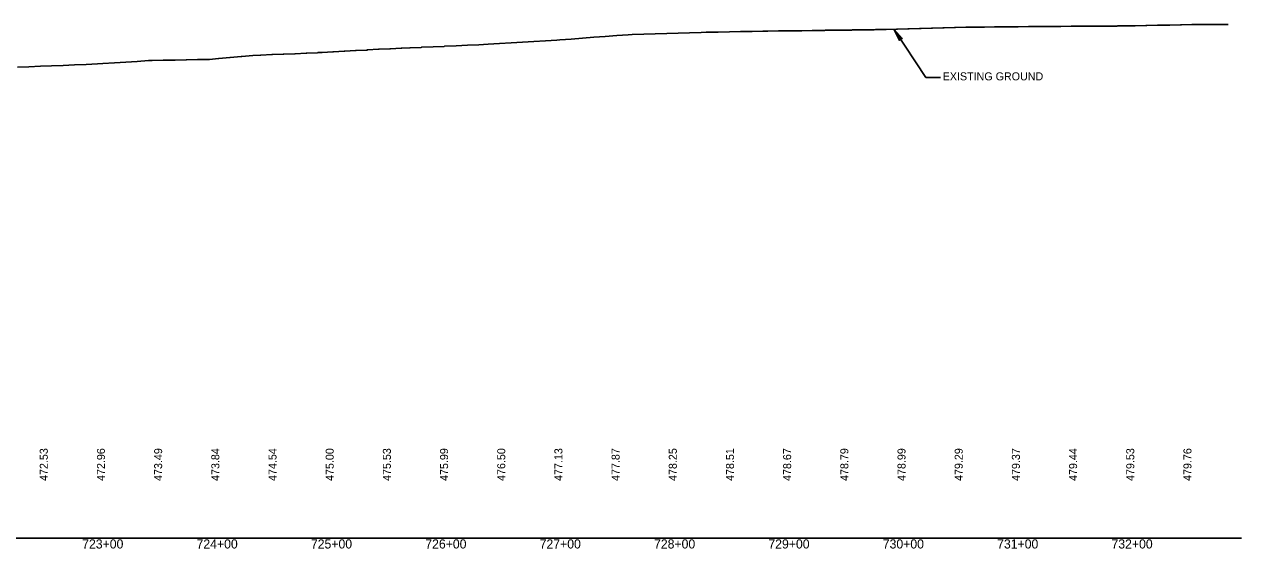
# Model space of a CAD drawing. Extents: x 2017200 to 2047700, y 854850 to 893350.
# Drawn here: x 2025936 to 2027000, y 889091 to 889549 of the extents above; entities that cross this region are included whole.
import ezdxf

# ---------------------------------------------------------------- set-up
doc = ezdxf.new("R2010")
doc.units = 0
for name, color, linetype in [('RD_DDB_Profile_EX', 7, 'Continuous'), ('RD_DDB_Profile_Lbl', 7, 'Continuous'), ('RD_DDB_StaTX', 7, 'Continuous'), ('RD_DDB_StripGrade', 7, 'Continuous'), ('RD_GPK_Profile_Cell', 7, 'Continuous')]:
    doc.layers.add(name, color=color, linetype=linetype)

msp = doc.modelspace()

# ---------------------------------------------------------------- linework, layer by layer
at = {"layer": 'RD_DDB_Profile_EX'}
msp.add_lwpolyline([(2025929.6, 889511.4), (2025939.6, 889511.8), (2025949.6, 889512.3), (2025959.5, 889512.7), (2025969.5, 889513.1), (2025979.6, 889513.5), (2025989.6, 889513.9), (2025999.6, 889514.3), (2026004.2, 889514.6), (2026014.4, 889515.3), (2026024.4, 889515.9), (2026034.4, 889516.6), (2026044.1, 889517.2), (2026047.4, 889517.3), (2026057.1, 889517.5), (2026057.4, 889517.5), (2026067.1, 889517.7), (2026067.4, 889517.7), (2026077.1, 889517.9), (2026077.4, 889517.9), (2026087.1, 889518.1), (2026087.4, 889518.1), (2026097.1, 889518.3), (2026097.4, 889518.3), (2026105.3, 889519), (2026105.7, 889519.1), (2026115.3, 889520), (2026115.7, 889520), (2026125.3, 889520.9), (2026125.7, 889520.9), (2026135.3, 889521.8), (2026142, 889522), (2026142.5, 889522.1), (2026152, 889522.5), (2026152.5, 889522.5), (2026162, 889522.9), (2026162.5, 889522.9), (2026172, 889523.3), (2026172.5, 889523.3), (2026182, 889523.7), (2026182.5, 889523.8), (2026192, 889524.1), (2026192.3, 889524.2), (2026195.3, 889524.3), (2026195.9, 889524.4), (2026205.3, 889524.9), (2026205.9, 889524.9), (2026215.3, 889525.4), (2026215.9, 889525.5), (2026225.3, 889526), (2026225.8, 889526), (2026235.2, 889526.5), (2026235.8, 889526.6), (2026245.2, 889527.1), (2026245.8, 889527.1), (2026255.2, 889527.6), (2026255.8, 889527.6), (2026265.1, 889528.1), (2026265.6, 889528.1), (2026272.6, 889528.4), (2026273.1, 889528.4), (2026282.6, 889528.8), (2026282.9, 889528.9), (2026283.2, 889528.9), (2026293, 889529.3), (2026302.7, 889529.7), (2026303, 889529.8), (2026313.2, 889530.2), (2026323.2, 889530.6), (2026333, 889531), (2026341.2, 889531.5), (2026351.2, 889532.1), (2026361.2, 889532.7), (2026371.2, 889533.4), (2026381.2, 889534), (2026391.3, 889534.6), (2026401.2, 889535.2), (2026403.7, 889535.4), (2026413.7, 889536.1), (2026423.7, 889536.9), (2026433.7, 889537.6), (2026443.6, 889538.4), (2026453.6, 889539.1), (2026463.6, 889539.8), (2026467.2, 889540), (2026477.2, 889540.3), (2026487.3, 889540.6), (2026497.3, 889540.9), (2026507.3, 889541.2), (2026517.3, 889541.6), (2026527.3, 889541.9), (2026531.8, 889542), (2026541.5, 889542.2), (2026542.2, 889542.2), (2026552.1, 889542.4), (2026561.8, 889542.6), (2026562.2, 889542.6), (2026571.9, 889542.8), (2026581.3, 889543), (2026581.9, 889543.1), (2026585, 889543.1), (2026585.6, 889543.1), (2026595, 889543.2), (2026595.7, 889543.2), (2026605, 889543.3), (2026605.7, 889543.3), (2026615, 889543.4), (2026615.3, 889543.4), (2026624.5, 889543.5), (2026625.3, 889543.5), (2026634.5, 889543.6), (2026635.3, 889543.6), (2026636, 889543.7), (2026645.1, 889543.8), (2026648.7, 889543.8), (2026649.6, 889543.9), (2026658.8, 889543.9), (2026659.8, 889544), (2026668.8, 889544.1), (2026669.8, 889544.1), (2026678.8, 889544.2), (2026679.8, 889544.3), (2026688.8, 889544.4), (2026689.3, 889544.4), (2026698.2, 889544.7), (2026699.2, 889544.7), (2026708.2, 889545), (2026709.2, 889545), (2026718.2, 889545.3), (2026719.2, 889545.3), (2026719.8, 889545.4), (2026728.8, 889545.6), (2026729.8, 889545.6), (2026738.8, 889545.9), (2026739.8, 889545.9), (2026748.8, 889546.2), (2026749.8, 889546.2), (2026758.8, 889546.5), (2026759.1, 889546.5), (2026764, 889546.6), (2026765.1, 889546.6), (2026774, 889546.6), (2026775.1, 889546.6), (2026784, 889546.7), (2026785.1, 889546.7), (2026794, 889546.8), (2026795, 889546.8), (2026804, 889546.8), (2026804.5, 889546.8), (2026813.5, 889546.9), (2026814.5, 889546.9), (2026823.5, 889547), (2026824.5, 889547), (2026833.6, 889547), (2026834.5, 889547.1), (2026840.9, 889547.1), (2026841.8, 889547.1), (2026850.9, 889547.2), (2026851.6, 889547.2), (2026860.7, 889547.2), (2026861.6, 889547.2), (2026870.8, 889547.3), (2026871.6, 889547.3), (2026880.8, 889547.4), (2026881.6, 889547.4), (2026890.8, 889547.4), (2026891.6, 889547.5), (2026900.8, 889547.5), (2026901.6, 889547.5), (2026906.2, 889547.6), (2026907, 889547.7), (2026916.2, 889547.9), (2026917.1, 889547.9), (2026926.4, 889548.1), (2026927.3, 889548.1), (2026936.4, 889548.3), (2026937.3, 889548.3), (2026946.4, 889548.5), (2026947.4, 889548.6), (2026956.4, 889548.8), (2026957.1, 889548.8), (2026958.1, 889548.8), (2026967, 889548.8), (2026968.2, 889548.9), (2026977, 889548.9), (2026977.7, 889548.9), (2026986.4, 889548.9), (2026987.8, 889548.9), (2026988.2, 889548.9)], dxfattribs=at)
at = {"layer": 'RD_DDB_Profile_Lbl'}
for p, q in [((2026723.8, 889502.6), (2026696.3, 889544.4)), ((2026736.7, 889502.6), (2026723.8, 889502.6))]:
    msp.add_line(p, q, dxfattribs=at)
msp.add_lwpolyline([(2026696.3, 889544.4), (2026700.8, 889534.9), (2026701.2, 889537), (2026703.3, 889536.5)], close=True, dxfattribs=at)
at = {"layer": 'RD_GPK_Profile_Cell'}
msp.add_line((2020500, 889100), (2027000, 889100), dxfattribs=at)

# ---------------------------------------------------------------- texts
at = {"layer": 'RD_DDB_Profile_Lbl'}
msp.add_text('EXISTING GROUND', height=7, dxfattribs=at).set_placement((2026738.6, 889500))
at = {"layer": 'RD_DDB_StaTX'}
for s, p in [('723+00', (2025986.2, 889091)), ('724+00', (2026086.2, 889091)), ('725+00', (2026186.2, 889091)), ('726+00', (2026286.2, 889091)), ('727+00', (2026386.2, 889091)), ('728+00', (2026486.2, 889091)), ('729+00', (2026586.2, 889091)), ('730+00', (2026686.2, 889091)), ('731+00', (2026786.2, 889091)), ('732+00', (2026886.2, 889091))]:
    msp.add_text(s, height=8, dxfattribs=at).set_placement(p)
at = {"layer": 'RD_DDB_StripGrade'}
for s, p in [('472.53', (2025956.1, 889150)), ('472.96', (2026006.1, 889150)), ('473.49', (2026056.1, 889150)), ('473.84', (2026106.1, 889150)), ('474.54', (2026156.1, 889150)), ('475.00', (2026206.1, 889150)), ('475.53', (2026256.1, 889150)), ('475.99', (2026306.1, 889150)), ('476.50', (2026356.1, 889150)), ('477.13', (2026406.1, 889150)), ('477.87', (2026456.1, 889150)), ('478.25', (2026506.1, 889150)), ('478.51', (2026556.1, 889150)), ('478.67', (2026606.1, 889150)), ('478.79', (2026656.1, 889150)), ('478.99', (2026706.1, 889150)), ('479.29', (2026756.1, 889150)), ('479.37', (2026806.1, 889150)), ('479.44', (2026856.1, 889150)), ('479.53', (2026906.1, 889150)), ('479.76', (2026956.1, 889150))]:
    msp.add_text(s, height=7, rotation=90, dxfattribs=at).set_placement(p)

doc.saveas('drawing.dxf')
